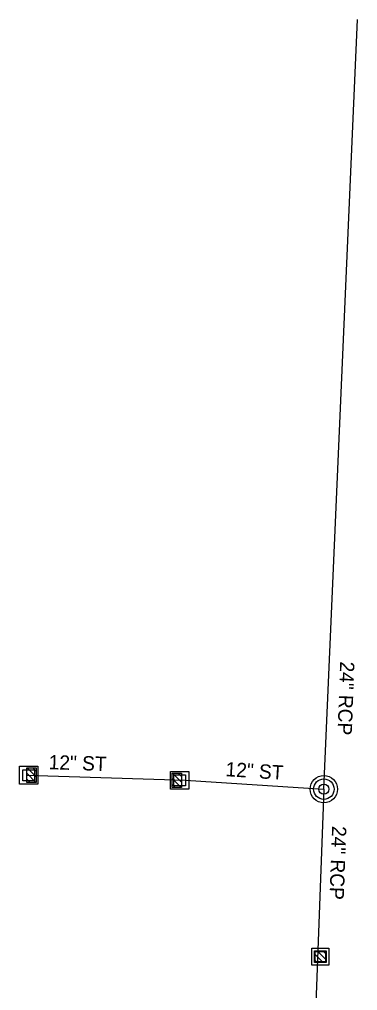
# Model space of a CAD drawing. Extents: x 1392719 to 1392850, y 437833 to 438309.
# Drawn here: x 1392746 to 1392812.1, y 438118.6 to 438308.7 of the extents above; entities that cross this region are included whole.
import ezdxf

# ---------------------------------------------------------------- set-up
doc = ezdxf.new("R2010")
doc.units = 0
for name, color, linetype in [('DR_X_Storm_Sewer', 7, 'Continuous'), ('RW_X_Fee_RW', 7, 'Continuous'), ('SV_X_Mon_Cells_Found', 7, 'Continuous'), ('TX_X_20', 7, 'Continuous')]:
    doc.layers.add(name, color=color, linetype=linetype)

msp = doc.modelspace()

# ---------------------------------------------------------------- linework, layer by layer
at = {"layer": 'DR_X_Storm_Sewer'}
for p, q in [((1392805.5, 438158.02), (1392812.09, 438308.69)), ((1392747.38, 438160.75), (1392778.42, 438159.75)), ((1392778.42, 438159.75), (1392805.5, 438158.02)), ((1392805.5, 438158.02), (1392802.55, 438077.47))]:
    msp.add_line(p, q, dxfattribs=at)
at = {"layer": 'RW_X_Fee_RW'}
for p, q in [((1392749.18, 438159.33), (1392747.38, 438161.13)), ((1392749.21, 438160.43), (1392747.48, 438162.16)), ((1392749.21, 438161.56), (1392748.61, 438162.16)), ((1392775.87, 438161.17), (1392777.67, 438159.37)), ((1392777, 438161.17), (1392777.67, 438160.5)), ((1392748.05, 438159.33), (1392747.38, 438160)), ((1392775.84, 438160.07), (1392777.58, 438158.34)), ((1392775.84, 438158.94), (1392776.44, 438158.34)), ((1392803.65, 438125.76), (1392805.34, 438124.07)), ((1392804.18, 438126.36), (1392805.94, 438124.6)), ((1392805.31, 438126.36), (1392805.94, 438125.73)), ((1392803.65, 438124.63), (1392804.21, 438124.07))]:
    msp.add_line(p, q, dxfattribs=at)
for points in [[(1392745.96, 438159), (1392745.96, 438162.5), (1392749.54, 438162.5), (1392749.54, 438159)], [(1392746.63, 438159.66), (1392746.63, 438161.83), (1392748.88, 438161.83), (1392748.88, 438159.66)], [(1392747.38, 438159.33), (1392747.38, 438162.16), (1392749.21, 438162.16), (1392749.21, 438159.33)], [(1392779.09, 438161.5), (1392779.09, 438158), (1392775.51, 438158), (1392775.51, 438161.5)], [(1392777.67, 438161.17), (1392777.67, 438158.34), (1392775.84, 438158.34), (1392775.84, 438161.17)], [(1392778.42, 438160.84), (1392778.42, 438158.67), (1392776.17, 438158.67), (1392776.17, 438160.84)], [(1392806.46, 438126.88), (1392806.46, 438123.55), (1392803.13, 438123.55), (1392803.13, 438126.88)], [(1392805.94, 438126.36), (1392805.94, 438124.07), (1392803.65, 438124.07), (1392803.65, 438126.36)], [(1392805.8, 438126.22), (1392805.8, 438124.22), (1392803.8, 438124.22), (1392803.8, 438126.22)]]:
    msp.add_lwpolyline(points, close=True, dxfattribs=at)
for radius in [2.67, 2, 1]:
    msp.add_circle((1392805.5, 438158.02), radius, dxfattribs=at)
at = {"layer": 'SV_X_Mon_Cells_Found'}
for p, q in [((1392747.75, 438161.83), (1392747.75, 438161.83)), ((1392745.96, 438160.75), (1392745.96, 438160.75)), ((1392746.63, 438160.75), (1392746.63, 438160.75)), ((1392747.38, 438160.75), (1392747.38, 438160.75)), ((1392747.38, 438160.75), (1392747.38, 438160.75)), ((1392747.75, 438160.75), (1392747.75, 438160.75)), ((1392747.75, 438160.75), (1392747.75, 438160.75)), ((1392747.75, 438159.66), (1392747.75, 438159.66)), ((1392748.88, 438160.75), (1392748.88, 438160.75)), ((1392749.54, 438160.75), (1392749.54, 438160.75)), ((1392775.51, 438159.75), (1392775.51, 438159.75)), ((1392776.17, 438159.75), (1392776.17, 438159.75)), ((1392777.3, 438160.84), (1392777.3, 438160.84)), ((1392777.3, 438159.75), (1392777.3, 438159.75)), ((1392777.3, 438159.75), (1392777.3, 438159.75)), ((1392777.67, 438159.75), (1392777.67, 438159.75)), ((1392777.67, 438159.75), (1392777.67, 438159.75)), ((1392778.42, 438159.75), (1392778.42, 438159.75)), ((1392779.09, 438159.75), (1392779.09, 438159.75)), ((1392777.3, 438158.67), (1392777.3, 438158.67)), ((1392803.5, 438158.02), (1392803.5, 438158.02)), ((1392805.5, 438158.02), (1392805.5, 438158.02)), ((1392805.5, 438158.02), (1392805.5, 438158.02)), ((1392805.5, 438158.02), (1392805.5, 438158.02)), ((1392807.5, 438158.02), (1392807.5, 438158.02)), ((1392803.13, 438125.22), (1392803.13, 438125.22)), ((1392803.8, 438125.22), (1392803.8, 438125.22)), ((1392804.8, 438126.22), (1392804.8, 438126.22)), ((1392804.8, 438125.22), (1392804.8, 438125.22)), ((1392804.8, 438125.22), (1392804.8, 438125.22)), ((1392804.8, 438125.22), (1392804.8, 438125.22)), ((1392805.8, 438125.22), (1392805.8, 438125.22)), ((1392806.46, 438125.22), (1392806.46, 438125.22)), ((1392804.8, 438124.22), (1392804.8, 438124.22))]:
    msp.add_line(p, q, dxfattribs=at)
msp.add_circle((1392805.5, 438158.02), 2, dxfattribs=at)

# ---------------------------------------------------------------- texts
at = {"layer": 'TX_X_20'}
for s, rotation, p in [('24" RCP', 267.9078, (1392808.69, 438183.05)), ('12" ST', 358.1668, (1392751.65, 438161.92)), ('12" ST', 356.3443, (1392786.21, 438160.56)), ('24" RCP', 267.9078, (1392807.12, 438150.84))]:
    msp.add_text(s, height=2.8, rotation=rotation, dxfattribs=at).set_placement(p)

doc.saveas('drawing.dxf')
